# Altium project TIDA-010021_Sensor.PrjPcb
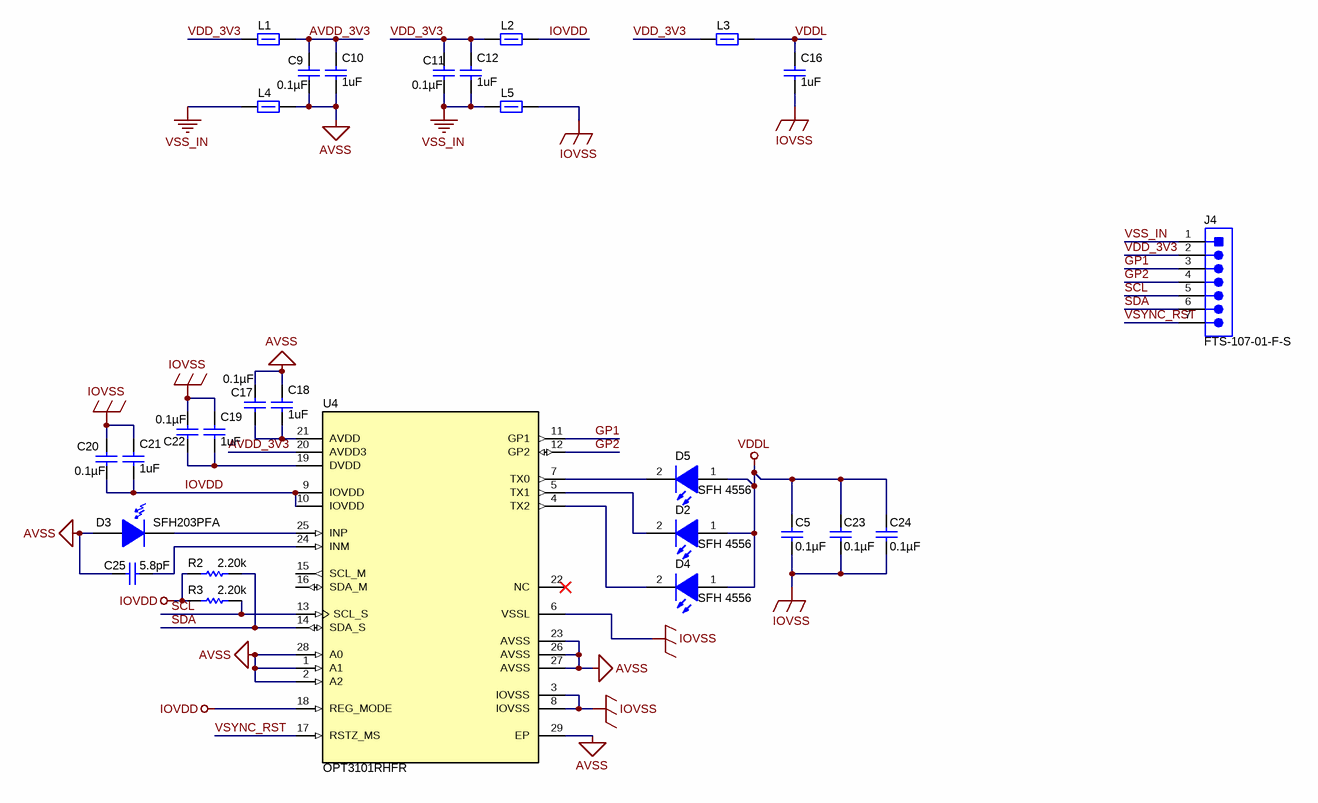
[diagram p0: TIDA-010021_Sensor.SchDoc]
EVM_Orderable: N/A; TID: 010021; TechSupport: http://www.ti.com/support; SCH_Rev: E1; PRJ_Title: Proximity Sensing Sensor Board; PRJ_Number: TIDA-010021; PRJ_Engineer: Richard Wang; PRJ_Customer: Public Release; PCB_Rev: E1; PCB_Layout: Richard Wang; CopyrightYear: 2018
3 sheets, 36 parts. Net scope: global (net labels, ports and power ports of the same name join across sheets).
Board file: TIDA-010021_Sensor.PcbDoc
Sheets:
  TIDA-010021_Sensor.SchDoc
  TIDA-010021_Sensor_CoverSheet.SchDoc
  TIDA-010021_Sensor_Hardware.SchDoc

## Sheet TIDA-010021_Sensor.SchDoc
size 431 x 279 mm; Date: Not shown in title block; ApprovedBy: Not shown in title block; CheckedBy: Not shown in title block; Author: Not shown in title block; CompanyName: Not shown in title block; DrawnBy: Richard Wang; Engineer: Not shown in title block; Organization: Not shown in title block; Address1: Not shown in title block; Address2: Not shown in title block; Address3: Not shown in title block; Address4: Not shown in title block; DocumentNumber: 1; Revision: Use project parameter SCH_Rev; SheetNumber: 2; SheetTotal: 3; PageSetup: Record=PageOptions¦CenterHorizontal=True¦CenterVertical=True¦PrintScale=1.00¦XCorrection=1.00¦YCorrection=1.00¦PrintKind=0¦BorderSize=5000000¦LeftOffset=0¦BottomOffset=0¦Orientation=2¦PaperLength=1000¦PaperWidth=1000¦Scale=100¦PaperSource=15¦PrintQuality=600¦MediaType=1¦DitherType=10¦PaperKind=Letter¦PrintScaleMode=1

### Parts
C5  ValueDisplayed: 0.1µF  [0402]  (hidden comment: 885012205037)
C9  ValueDisplayed: 0.1µF  [0402]  (hidden comment: 885012205037)
C10  value 1uF  [0402]  (hidden comment: GRM155R61A105KE15D)
C11  ValueDisplayed: 0.1µF  [0402]  (hidden comment: 885012205037)
C12  value 1uF  [0402]  (hidden comment: GRM155R61A105KE15D)
C16  value 1uF  [0402]  (hidden comment: GRM155R61A105KE15D)
C17  ValueDisplayed: 0.1µF  [0402]  (hidden comment: 885012205037)
C18  value 1uF  [0402]  (hidden comment: GRM155R61A105KE15D)
C19  value 1uF  [0402]  (hidden comment: GRM155R61A105KE15D)
C20  ValueDisplayed: 0.1µF  [0402]  (hidden comment: 885012205037)
C21  value 1uF  [0402]  (hidden comment: GRM155R61A105KE15D)
C22  ValueDisplayed: 0.1µF  [0402]  (hidden comment: 885012205037)
C23  ValueDisplayed: 0.1µF  [0402]  (hidden comment: 885012205037)
C24  ValueDisplayed: 0.1µF  [0402]  (hidden comment: 885012205037)
C25  value 5.8pF  [0402]  (hidden comment: GJM1555C1H5R8WB01D)
D2  SFH 4556  [SFH4556]
D3  SFH203PFA  [SFH203PFA]
D4  SFH 4556  [SFH4556]
D5  SFH 4556  [SFH4556]
J4  FTS-107-01-F-S  [Samtec_FTS-107-01-x-S]
L1  MMZ1005S182ET000  [MMZ1005-E]  (value not drawn)
L2  MMZ1005S182ET000  [MMZ1005-E]  (value not drawn)
L3  MMZ1005S182ET000  [MMZ1005-E]  (value not drawn)
L4  MMZ1005S182ET000  [MMZ1005-E]  (value not drawn)
L5  MMZ1005S182ET000  [MMZ1005-E]  (value not drawn)
R2  ValueDisplayed: 2.20k  [0402]  (hidden comment: RC0402FR-072K2L)
R3  ValueDisplayed: 2.20k  [0402]  (hidden comment: RC0402FR-072K2L)
U4  OPT3101RHFR  [RHF0028A]

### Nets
AVSS: C9.2 C10.2 C17.1 C18.1 C25.2 D3.1(A) L4.2 U4.1(A1) U4.2(A2) U4.23(AVSS) U4.26(AVSS) U4.27(AVSS) U4.28(A0) U4.29(EP)
IOVDD: C20.2 C21.2 L2.2 R2.1 R3.1 U4.9(IOVDD) U4.10(IOVDD) U4.18(REG_MODE)
IOVSS: C5.2 C16.2 C19.1 C20.1 C21.1 C22.1 C23.2 C24.2 L5.2 U4.3(IOVSS) U4.6(VSSL) U4.8(IOVSS)
VDDL: C5.1 C16.1 C23.1 C24.1 D2.1(A) D4.1(A) D5.1(A) L3.2
VSS_IN: C11.2 C12.2 J4.1 L4.1 L5.1
AVDD_3V3: C9.1 C10.1 L1.2 U4.20(AVDD3)
GP1: J4.3 U4.11(GP1)
GP2: J4.4 U4.12(GP2)
SCL: J4.5 R3.2 U4.13(SCL_S)
SDA: J4.6 R2.2 U4.14(SDA_S)
VDD_3V3: C11.1 C12.1 J4.2 L1.1 L2.1 L3.1
VSYNC_RST: J4.7 U4.17(RSTZ_MS)
NetC17_2: C17.2 C18.2 U4.21(AVDD)
NetC19_2: C19.2 C22.2 U4.19(DVDD)
NetC25_1: C25.1 U4.24(INM)
NetD2_2: D2.2(K) U4.5(TX1)
NetD3_2: D3.2(C) U4.25(INP)
NetD4_2: D4.2(K) U4.4(TX2)
NetD5_2: D5.2(K) U4.7(TX0)

Not connected (* = marked no-connect by the designer): U4 15(SCL_M) 16(SDA_M) 22(NC)*

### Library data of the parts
C5 C9 C11 C17 C20 C22-C24 = 885012205037: CAP, CERM, 0.1 µF, 16 V, +/- 10%, X7R, 0402; Manufacturer: Wurth Elektronik; Polarized: N; CompType: Capacitor; Value: 0.1uF; U/M: EA; Cap_F: 0.0000001; Tolerance_%: 10; Value1: Unknown; VDC_V: 16; Value2: 16V; TaMin_C: -55; TaMax_C: 125; SizeArea_mm2: 0.5; SizeAreaWB_mm2: 3; SizeX_mm: 1; SizeZ_mm: 0.6; AEC Category: Q200
C10 C12 C16 C18 C19 C21 = CMP-0006563-2: CAP, CERM, 1 uF, 10 V, +/- 10%, X5R, 0402; Manufacturer: MuRata; TaMin_C: -55°C; Polarized: N; SizeAreaWB_mm2: 3; Value1: Unknown; U/M: EA; TaMax_C: 85°C; SizeZ_mm: 0.6; SizeX_mm: 1; SizeY_mm: 0.5; Value2: 10V; CompType: Capacitor; Cap_F: 1µF; AEC Category: Q200
C25 = CMP-0084115-1: CAP, CERM, 5.8pF, 50 V,+/- 0.8%, C0G/NP0, 0402; Manufacturer: MuRata; SizeAreaWB_mm2: 3; SizeArea_mm2: 0.5; AEC Qualified: N; AEC Category: Q200; TaMax_C: 125°C; SizeZ_mm: 0.6; TaMin_C: -55°C; VDC_V: 50V; U/M: EA; CompType: Capacitor; SizeX_mm: 1
D2 D4 D5 = CMP-0077984-1: LED, Infrared, TH; Manufacturer: OSRAM; SizeAreaWB_mm2: 53.8125; Vr_V: 5V; Power_TotalModule: 180mW; Angle: 40; SizeArea_mm2: 28.4625; SizeZ_mm: 11.1; Io_A: 1dA; Vf_V: 1.5V; SizeY_mm: 5.5; U/M: EA; Value1: .18W; SizeX_mm: 5.175
D3 = CMP-0084123-1: Silicon PIN Photodiode, TH; Manufacturer: OSRAM; SizeArea_mm2: 32.49; SizeAreaWB_mm2: 59.29; SizeY_mm: 5.7; SizeZ_mm: 7.75
J4 = CMP-0075532-1: Header, 1.27mm, 7x1, Gold, TH; Manufacturer: Samtec; Pitch_mm: 1.27; Gender: Male; CT: False; Shrouded: N; Row_Count: 1; CNHeader: True
L1-L5 = CMP-0080017-1: Inductor, Ferrite Bead, Ferrite, 0.2 A, 2.1 ohm, SMD; Manufacturer: TDK; SizeAreaWB_mm2: 3; SizeArea_mm2: 0.5; AEC Qualified: N; AEC Category: Q200; SizeZ_mm: 0.55; Imax_A: 2dA; Value2: 0.2A; Value1: 2.1 ohm; DCR_ohm: 2.1; SizeX_mm: 1
R2 R3 = RC0402FR-072K2L: RES, 2.20 k, 1%, 0.063 W, 0402; Manufacturer: Yageo America; CompType: Resistor; Value: 2.20k; Res_ohm: 2200; Value_Code: 2k20; Tolerance_%: 1; Power_W: 0.063; Value2: 0.063W; TempCo: 100 ppm/C; SizeArea_mm2: 0.5; SizeZ_mm: 0.6; U/M: EA; AEC Category: Q200; AEC Qualified: N
U4 = CMP-0074632-3: Long Range Proximity/Depth Sensor, RHF0028A (VQFN-28); Alternate PartNumber: OPT3101RHFT; Manufacturer: Texas Instruments; SizeZ_mm: 1.0; SizeX_mm: 4.0; SizeY_mm: 5.0; SizeArea_mm2: 20.0; CompType: IC; U/M: EA; SizeAreaWB_mm2: 42.0

## Sheet TIDA-010021_Sensor_CoverSheet.SchDoc
size 431 x 279 mm; Date: Not shown in title block; ApprovedBy: Not shown in title block; CheckedBy: Not shown in title block; Author: Not shown in title block; CompanyName: Not shown in title block; DrawnBy: Richard Wang; Engineer: Not shown in title block; Organization: Not shown in title block; Address1: Not shown in title block; Address2: Not shown in title block; Address3: Not shown in title block; Address4: Not shown in title block; DocumentNumber: 1; Revision: Use project parameter SCH_Rev; SheetNumber: 1; SheetTotal: 3; PageSetup: Record=PageOptions¦CenterHorizontal=True¦CenterVertical=True¦PrintScale=1.00¦XCorrection=1.00¦YCorrection=1.00¦PrintKind=0¦BorderSize=5000000¦LeftOffset=0¦BottomOffset=0¦Orientation=2¦PaperLength=1000¦PaperWidth=1000¦Scale=100¦PaperSource=15¦PrintQuality=600¦MediaType=1¦DitherType=10¦PaperKind=Letter¦PrintScaleMode=1
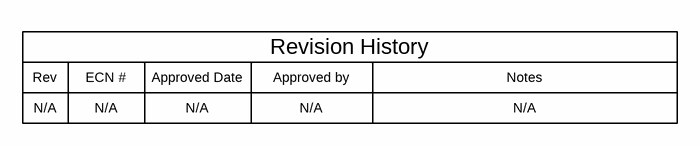
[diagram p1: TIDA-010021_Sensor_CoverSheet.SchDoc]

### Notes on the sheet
- Rev
- N/A
- ECN #
- Approved Date
- Approved by
- Revision History
- Notes

## Sheet TIDA-010021_Sensor_Hardware.SchDoc
size 431 x 279 mm; Date: Not shown in title block; ApprovedBy: Not shown in title block; CheckedBy: Not shown in title block; Author: Not shown in title block; CompanyName: Not shown in title block; DrawnBy: Richard Wang; Engineer: Richard Wang; Organization: Not shown in title block; Address1: Not shown in title block; Address2: Not shown in title block; Address3: Not shown in title block; Address4: Not shown in title block; DocumentNumber: 1; Revision: Use project parameter SCH_Rev; SheetNumber: 3; SheetTotal: 3; PageSetup: Record=PageOptions¦CenterHorizontal=True¦CenterVertical=True¦PrintScale=1.00¦XCorrection=1.00¦YCorrection=1.00¦PrintKind=0¦BorderSize=5000000¦LeftOffset=0¦BottomOffset=0¦Orientation=2¦PaperLength=1000¦PaperWidth=1000¦Scale=100¦PaperSource=15¦PrintQuality=600¦MediaType=1¦DitherType=10¦PaperKind=Letter¦PrintScaleMode=1
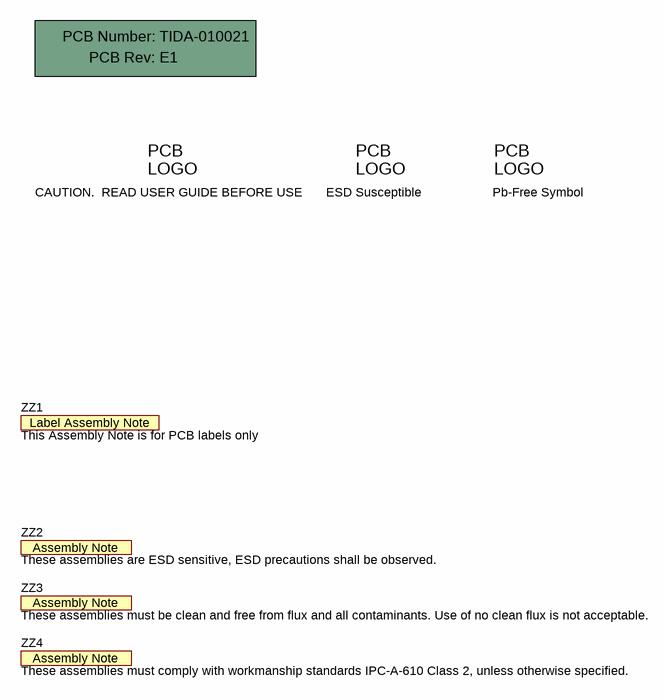
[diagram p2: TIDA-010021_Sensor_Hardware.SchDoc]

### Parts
!PCB  Printed Circuit Board  (value not drawn)  (mechanical)
Caution  CAUTION.  READ USER GUIDE BEFORE USE  [IEC_Caution_small]  (no BOM)
ESD  ESD Susceptible  [ESD_Overlay_small]  (no BOM)
Logo2  Pb-Free Symbol  [Pb-Free_Overlay_Small]  (no BOM)
ZZ1  This Assembly Note is for PCB labels only  [AssemblyNoteLabel]  (no BOM)
ZZ2  These assemblies are ESD sensitive, ESD precautions shall be observed.  [AssemblyNote]  (no BOM)
ZZ3  These assemblies must be clean and free from flux and all contaminants. Use of no clean flux is not acceptable.  [AssemblyNote]  (no BOM)
ZZ4  These assemblies must comply with workmanship standards IPC-A-610 Class 2, unless otherwise specified.  [AssemblyNote]  (no BOM)

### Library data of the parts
!PCB = PCB: Manufacturer: Any; PartNumber: TIDA-010021; SymbolCreator: a0412235
Caution = IEC_Caution: IEC 61010-1 Caution Warning; SymbolCreator: a0412235
ESD = ESD_Susceptible: ESD Susceptible Symbol; SymbolCreator: a0412235
Logo2 = Pb-Free: SymbolCreator: a0412235
ZZ1 = AssemblyNoteLabel: SymbolCreator: a0412235
ZZ2-ZZ4 = AssemblyNote: SymbolCreator: codlsc

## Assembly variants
001: not fitted FID1 FID2 FID3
